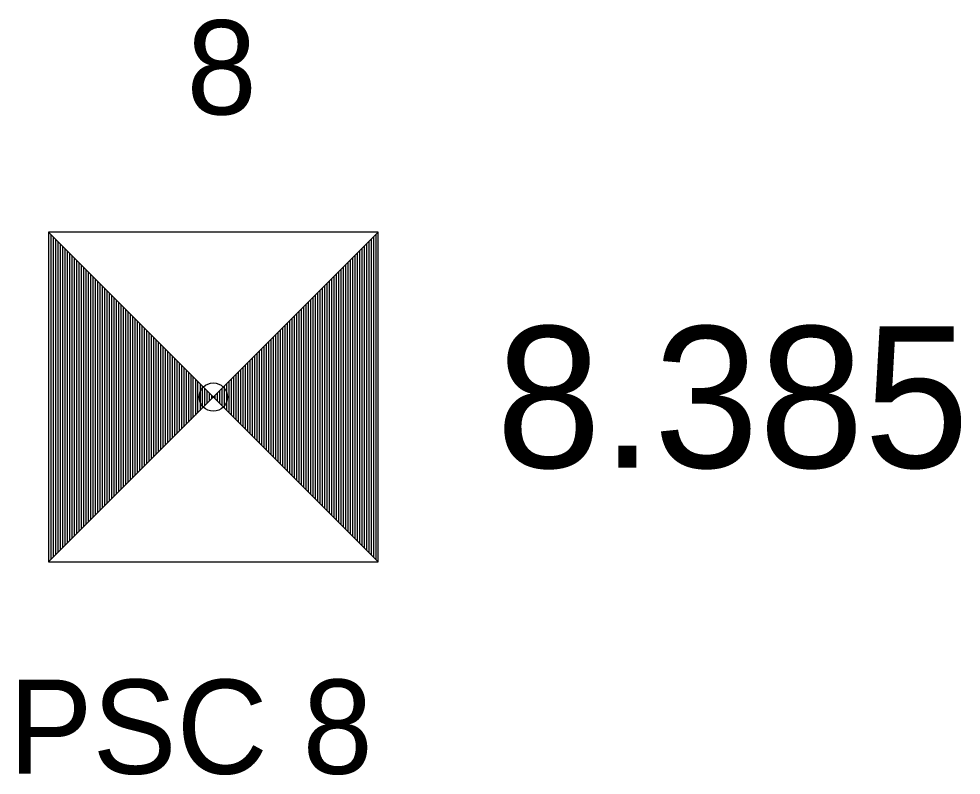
# Model space of a CAD drawing. Extents: x 2042211 to 2045853, y 303080 to 309569.
# Drawn here: x 2044977.46 to 2044987.46, y 304059.71 to 304067.74 of the extents above; entities that cross this region are included whole.
import ezdxf

# ---------------------------------------------------------------- set-up
doc = ezdxf.new("R2010")
doc.units = 0
for name, color, linetype in [('BR_500YR_SCOUR', 7, 'Continuous'), ('RD_HC_Survey_ELEV', 7, 'Continuous'), ('RD_HC_txCode', 7, 'Continuous')]:
    doc.layers.add(name, color=color, linetype=linetype)

msp = doc.modelspace()

# ---------------------------------------------------------------- linework, layer by layer
at = {"layer": 'BR_500YR_SCOUR'}
for p, q in [((2044977.7744, 304065.4769), (2044981.2744, 304061.9769)), ((2044981.2744, 304065.4769), (2044977.7744, 304061.9769)), ((2044977.7992, 304065.4521), (2044977.7992, 304062.0017)), ((2044981.2496, 304065.4521), (2044981.2496, 304062.0017)), ((2044977.8239, 304065.4274), (2044977.8239, 304062.0264)), ((2044977.8487, 304065.4026), (2044977.8487, 304062.0512)), ((2044977.8734, 304065.3779), (2044977.8734, 304062.0759)), ((2044977.8982, 304065.3531), (2044977.8982, 304062.1007)), ((2044981.1506, 304065.3531), (2044981.1506, 304062.1007)), ((2044981.1754, 304065.3779), (2044981.1754, 304062.0759)), ((2044981.2001, 304065.4026), (2044981.2001, 304062.0512)), ((2044981.2249, 304065.4274), (2044981.2249, 304062.0264)), ((2044977.9229, 304065.3284), (2044977.9229, 304062.1254)), ((2044977.9476, 304065.3037), (2044977.9476, 304062.1501)), ((2044977.9724, 304065.2789), (2044977.9724, 304062.1749)), ((2044977.9971, 304065.2542), (2044977.9971, 304062.1996)), ((2044981.0517, 304065.2542), (2044981.0517, 304062.1996)), ((2044981.0764, 304065.2789), (2044981.0764, 304062.1749)), ((2044981.1012, 304065.3037), (2044981.1012, 304062.1501)), ((2044981.1259, 304065.3284), (2044981.1259, 304062.1254)), ((2044978.0219, 304065.2294), (2044978.0219, 304062.2244)), ((2044978.0466, 304065.2047), (2044978.0466, 304062.2491)), ((2044978.0714, 304065.1799), (2044978.0714, 304062.2739)), ((2044978.0961, 304065.1552), (2044978.0961, 304062.2986)), ((2044980.9527, 304065.1552), (2044980.9527, 304062.2986)), ((2044980.9774, 304065.1799), (2044980.9774, 304062.2739)), ((2044981.0022, 304065.2047), (2044981.0022, 304062.2491)), ((2044981.0269, 304065.2294), (2044981.0269, 304062.2244)), ((2044978.1209, 304065.1304), (2044978.1209, 304062.3234)), ((2044978.1456, 304065.1057), (2044978.1456, 304062.3481)), ((2044978.1704, 304065.0809), (2044978.1704, 304062.3729)), ((2044978.1951, 304065.0562), (2044978.1951, 304062.3976)), ((2044980.8537, 304065.0562), (2044980.8537, 304062.3976)), ((2044980.8784, 304065.0809), (2044980.8784, 304062.3729)), ((2044980.9032, 304065.1057), (2044980.9032, 304062.3481)), ((2044980.9279, 304065.1304), (2044980.9279, 304062.3234)), ((2044978.2199, 304065.0314), (2044978.2199, 304062.4224)), ((2044978.2446, 304065.0067), (2044978.2446, 304062.4471)), ((2044978.2694, 304064.9819), (2044978.2694, 304062.4719)), ((2044978.2941, 304064.9572), (2044978.2941, 304062.4966)), ((2044980.7547, 304064.9572), (2044980.7547, 304062.4966)), ((2044980.7794, 304064.9819), (2044980.7794, 304062.4719)), ((2044980.8042, 304065.0067), (2044980.8042, 304062.4471)), ((2044980.8289, 304065.0314), (2044980.8289, 304062.4224)), ((2044978.3189, 304064.9324), (2044978.3189, 304062.5214)), ((2044978.3436, 304064.9077), (2044978.3436, 304062.5461)), ((2044978.3684, 304064.8829), (2044978.3684, 304062.5709)), ((2044978.3931, 304064.8582), (2044978.3931, 304062.5956)), ((2044980.6557, 304064.8582), (2044980.6557, 304062.5956)), ((2044980.6804, 304064.8829), (2044980.6804, 304062.5709)), ((2044980.7052, 304064.9077), (2044980.7052, 304062.5461)), ((2044980.7299, 304064.9324), (2044980.7299, 304062.5214)), ((2044978.4179, 304064.8334), (2044978.4179, 304062.6204)), ((2044978.4426, 304064.8087), (2044978.4426, 304062.6451)), ((2044978.4674, 304064.7839), (2044978.4674, 304062.6699)), ((2044978.4921, 304064.7592), (2044978.4921, 304062.6946)), ((2044980.5567, 304064.7592), (2044980.5567, 304062.6946)), ((2044980.5814, 304064.7839), (2044980.5814, 304062.6699)), ((2044980.6062, 304064.8087), (2044980.6062, 304062.6451)), ((2044980.6309, 304064.8334), (2044980.6309, 304062.6204)), ((2044978.5169, 304064.7344), (2044978.5169, 304062.7194)), ((2044978.5416, 304064.7097), (2044978.5416, 304062.7441)), ((2044978.5664, 304064.6849), (2044978.5664, 304062.7689)), ((2044978.5911, 304064.6602), (2044978.5911, 304062.7936)), ((2044980.4577, 304064.6602), (2044980.4577, 304062.7936)), ((2044980.4824, 304064.6849), (2044980.4824, 304062.7689)), ((2044980.5072, 304064.7097), (2044980.5072, 304062.7441)), ((2044980.5319, 304064.7344), (2044980.5319, 304062.7194)), ((2044978.6159, 304064.6354), (2044978.6159, 304062.8184)), ((2044978.6406, 304064.6107), (2044978.6406, 304062.8431)), ((2044978.6654, 304064.5859), (2044978.6654, 304062.8679)), ((2044978.6901, 304064.5612), (2044978.6901, 304062.8926)), ((2044980.3587, 304064.5612), (2044980.3587, 304062.8926)), ((2044980.3834, 304064.5859), (2044980.3834, 304062.8679)), ((2044980.4082, 304064.6107), (2044980.4082, 304062.8431)), ((2044980.4329, 304064.6354), (2044980.4329, 304062.8184)), ((2044978.7149, 304064.5364), (2044978.7149, 304062.9174)), ((2044978.7396, 304064.5117), (2044978.7396, 304062.9421)), ((2044978.7644, 304064.4869), (2044978.7644, 304062.9669)), ((2044978.7891, 304064.4622), (2044978.7891, 304062.9916)), ((2044980.2597, 304064.4622), (2044980.2597, 304062.9916)), ((2044980.2844, 304064.4869), (2044980.2844, 304062.9669)), ((2044980.3092, 304064.5117), (2044980.3092, 304062.9421)), ((2044980.3339, 304064.5364), (2044980.3339, 304062.9174)), ((2044978.8139, 304064.4374), (2044978.8139, 304063.0164)), ((2044978.8386, 304064.4127), (2044978.8386, 304063.0411)), ((2044978.8633, 304064.388), (2044978.8633, 304063.0658)), ((2044978.8881, 304064.3632), (2044978.8881, 304063.0906)), ((2044980.1607, 304064.3632), (2044980.1607, 304063.0906)), ((2044980.1855, 304064.388), (2044980.1855, 304063.0658)), ((2044980.2102, 304064.4127), (2044980.2102, 304063.0411)), ((2044980.2349, 304064.4374), (2044980.2349, 304063.0164)), ((2044978.9128, 304064.3385), (2044978.9128, 304063.1153)), ((2044978.9376, 304064.3137), (2044978.9376, 304063.1401)), ((2044978.9623, 304064.289), (2044978.9623, 304063.1648)), ((2044978.9871, 304064.2642), (2044978.9871, 304063.1896)), ((2044980.0617, 304064.2642), (2044980.0617, 304063.1896)), ((2044980.0865, 304064.289), (2044980.0865, 304063.1648)), ((2044980.1112, 304064.3137), (2044980.1112, 304063.1401)), ((2044980.136, 304064.3385), (2044980.136, 304063.1153)), ((2044979.0118, 304064.2395), (2044979.0118, 304063.2143)), ((2044979.0366, 304064.2147), (2044979.0366, 304063.2391)), ((2044979.0613, 304064.19), (2044979.0613, 304063.2638)), ((2044979.0861, 304064.1652), (2044979.0861, 304063.2886)), ((2044979.9627, 304064.1652), (2044979.9627, 304063.2886)), ((2044979.9875, 304064.19), (2044979.9875, 304063.2638)), ((2044980.0122, 304064.2147), (2044980.0122, 304063.2391)), ((2044980.037, 304064.2395), (2044980.037, 304063.2143)), ((2044979.1108, 304064.1405), (2044979.1108, 304063.3133)), ((2044979.1356, 304064.1157), (2044979.1356, 304063.3381)), ((2044979.1603, 304064.091), (2044979.1603, 304063.3628)), ((2044979.1851, 304064.0662), (2044979.1851, 304063.3876)), ((2044979.8637, 304064.0662), (2044979.8637, 304063.3876)), ((2044979.8885, 304064.091), (2044979.8885, 304063.3628)), ((2044979.9132, 304064.1157), (2044979.9132, 304063.3381)), ((2044979.938, 304064.1405), (2044979.938, 304063.3133)), ((2044979.2098, 304064.0415), (2044979.2098, 304063.4123)), ((2044979.2346, 304064.0167), (2044979.2346, 304063.4371)), ((2044979.2593, 304063.992), (2044979.2593, 304063.4618)), ((2044979.2841, 304063.9672), (2044979.2841, 304063.4866)), ((2044979.7647, 304063.9672), (2044979.7647, 304063.4866)), ((2044979.7895, 304063.992), (2044979.7895, 304063.4618)), ((2044979.8142, 304064.0167), (2044979.8142, 304063.4371)), ((2044979.839, 304064.0415), (2044979.839, 304063.4123)), ((2044979.3088, 304063.9425), (2044979.3088, 304063.5113)), ((2044979.3336, 304063.9177), (2044979.3336, 304063.5361)), ((2044979.3583, 304063.893), (2044979.3583, 304063.5608)), ((2044979.3831, 304063.8682), (2044979.3831, 304063.5856)), ((2044979.6657, 304063.8682), (2044979.6657, 304063.5856)), ((2044979.6905, 304063.893), (2044979.6905, 304063.5608)), ((2044979.7152, 304063.9177), (2044979.7152, 304063.5361)), ((2044979.74, 304063.9425), (2044979.74, 304063.5113)), ((2044979.4078, 304063.8435), (2044979.4078, 304063.6103)), ((2044979.4326, 304063.8187), (2044979.4326, 304063.6351)), ((2044979.4573, 304063.794), (2044979.4573, 304063.6598)), ((2044979.4821, 304063.7692), (2044979.4821, 304063.6846)), ((2044979.5667, 304063.7692), (2044979.5667, 304063.6846)), ((2044979.5915, 304063.794), (2044979.5915, 304063.6598)), ((2044979.6162, 304063.8187), (2044979.6162, 304063.6351)), ((2044979.641, 304063.8435), (2044979.641, 304063.6103)), ((2044979.5068, 304063.7445), (2044979.5068, 304063.7093)), ((2044979.542, 304063.7445), (2044979.542, 304063.7093))]:
    msp.add_line(p, q, dxfattribs=at)
msp.add_lwpolyline([(2044981.2744, 304065.4769), (2044977.7744, 304065.4769), (2044977.7744, 304061.9769), (2044981.2744, 304061.9769)], close=True, dxfattribs=at)
msp.add_circle((2044979.5244, 304063.7269), 0.15, dxfattribs=at)

# ---------------------------------------------------------------- texts
at = {"layer": 'RD_HC_Survey_ELEV'}
msp.add_text('8.385', height=1.5, dxfattribs=at).set_placement((2044982.5244, 304062.9769))
at = {"layer": 'RD_HC_txCode'}
for s, p in [('8', (2044979.2409, 304066.7269)), ('PSC 8', (2044977.3512, 304059.7269))]:
    msp.add_text(s, height=1, dxfattribs=at).set_placement(p)

doc.saveas('drawing.dxf')
